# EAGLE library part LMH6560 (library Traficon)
Quad, High-Speed, Closed-Loop Buffer
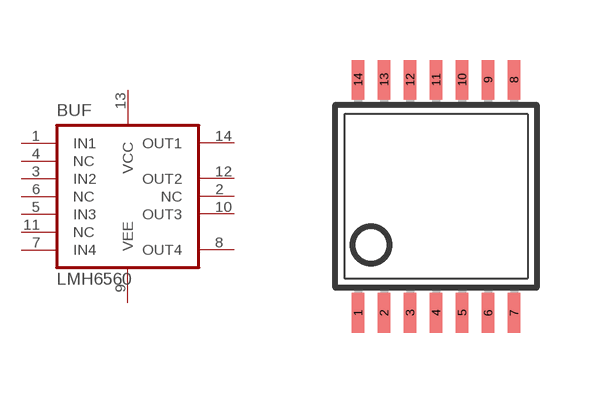
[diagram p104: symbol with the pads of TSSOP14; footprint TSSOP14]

Designator prefix BUF

## LMH6560MT  [TSSOP14]
1  IN1
2  NC
3  IN2
4  NC
5  IN3
6  NC
7  IN4
8  OUT4
9  VEE
10  OUT3
11  NC
12  OUT2
13  VCC
14  OUT1

## Footprint TSSOP14 (pad centres in mm)
Thin Shrink Small Outline Plastic 14 MAX3223-MAX3243.pdf
smd 0.305 x 0.991: 1 -1.95,-2.918; 2 -1.3,-2.918; 3 -0.65,-2.918; 4 0,-2.918; 5 0.65,-2.918; 6 1.3,-2.918; 7 1.95,-2.918; 8 1.95,2.918; 9 1.3,2.918; 10 0.65,2.918; 11 0,2.918; 12 -0.65,2.918; 13 -1.3,2.918; 14 -1.95,2.918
